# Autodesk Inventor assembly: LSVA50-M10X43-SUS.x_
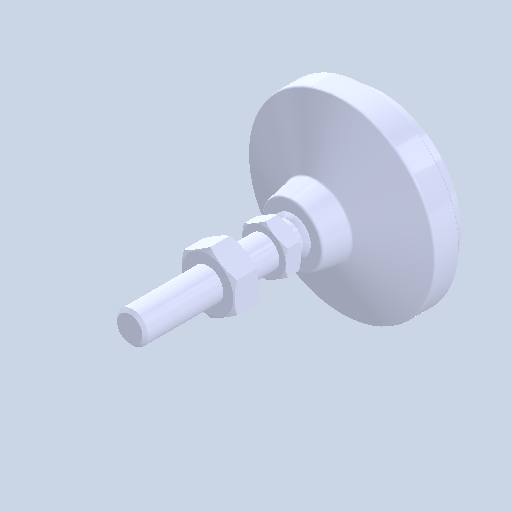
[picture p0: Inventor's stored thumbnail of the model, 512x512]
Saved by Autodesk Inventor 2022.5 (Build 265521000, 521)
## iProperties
Created: 2024-08
Part Number: LSVA50-M10X43-SUS.x_
Document SubType Name: Assembly
Designer: ImaoCorp
Author: ImaoCorp
Sending System: SOLIDWORKS 2022-2022290
MC: AMD64
MC_MODEL: Intel64 Family 6 Model 60 Stepping 3, GenuineIntel
OS: Windows_NT
FRU: Parasolid Version 33.1, build 260,  4-25-2022
FORMAT: text
GUISE: transmit
KEY: FILELSVA50-M10X43-SUS.x_t
DATE: Fri Aug 23 16:08:07 2024
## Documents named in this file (4)
- X:\14_SW2022-Inv2022\06_2024-10新製品(SME)\ELS_データ\l\lsva50-m10x43-sus\LSVA50-M10X43-SUS.x_.iam
- X:\14_SW2022-Inv2022\06_2024-10新製品(SME)\ELS_データ\l\lsva50-m10x43-sus\LSVA50-M10X43-SUS_01.ipt
- X:\14_SW2022-Inv2022\06_2024-10新製品(SME)\ELS_データ\l\lsva50-m10x43-sus\LSVA50-M10X43-SUS_02.ipt
- X:\14_SW2022-Inv2022\06_2024-10新製品(SME)\ELS_データ\l\lsva50-m10x43-sus\LSVA50-M10X43-SUS_03.ipt
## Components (3 placed, 3 different names)
1. LSVA50-M10X43-SUS_01
2. LSVA50-M10X43-SUS_02
3. LSVA50-M10X43-SUS_03
